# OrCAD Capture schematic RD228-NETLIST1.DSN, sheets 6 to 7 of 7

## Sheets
6 2: size A3
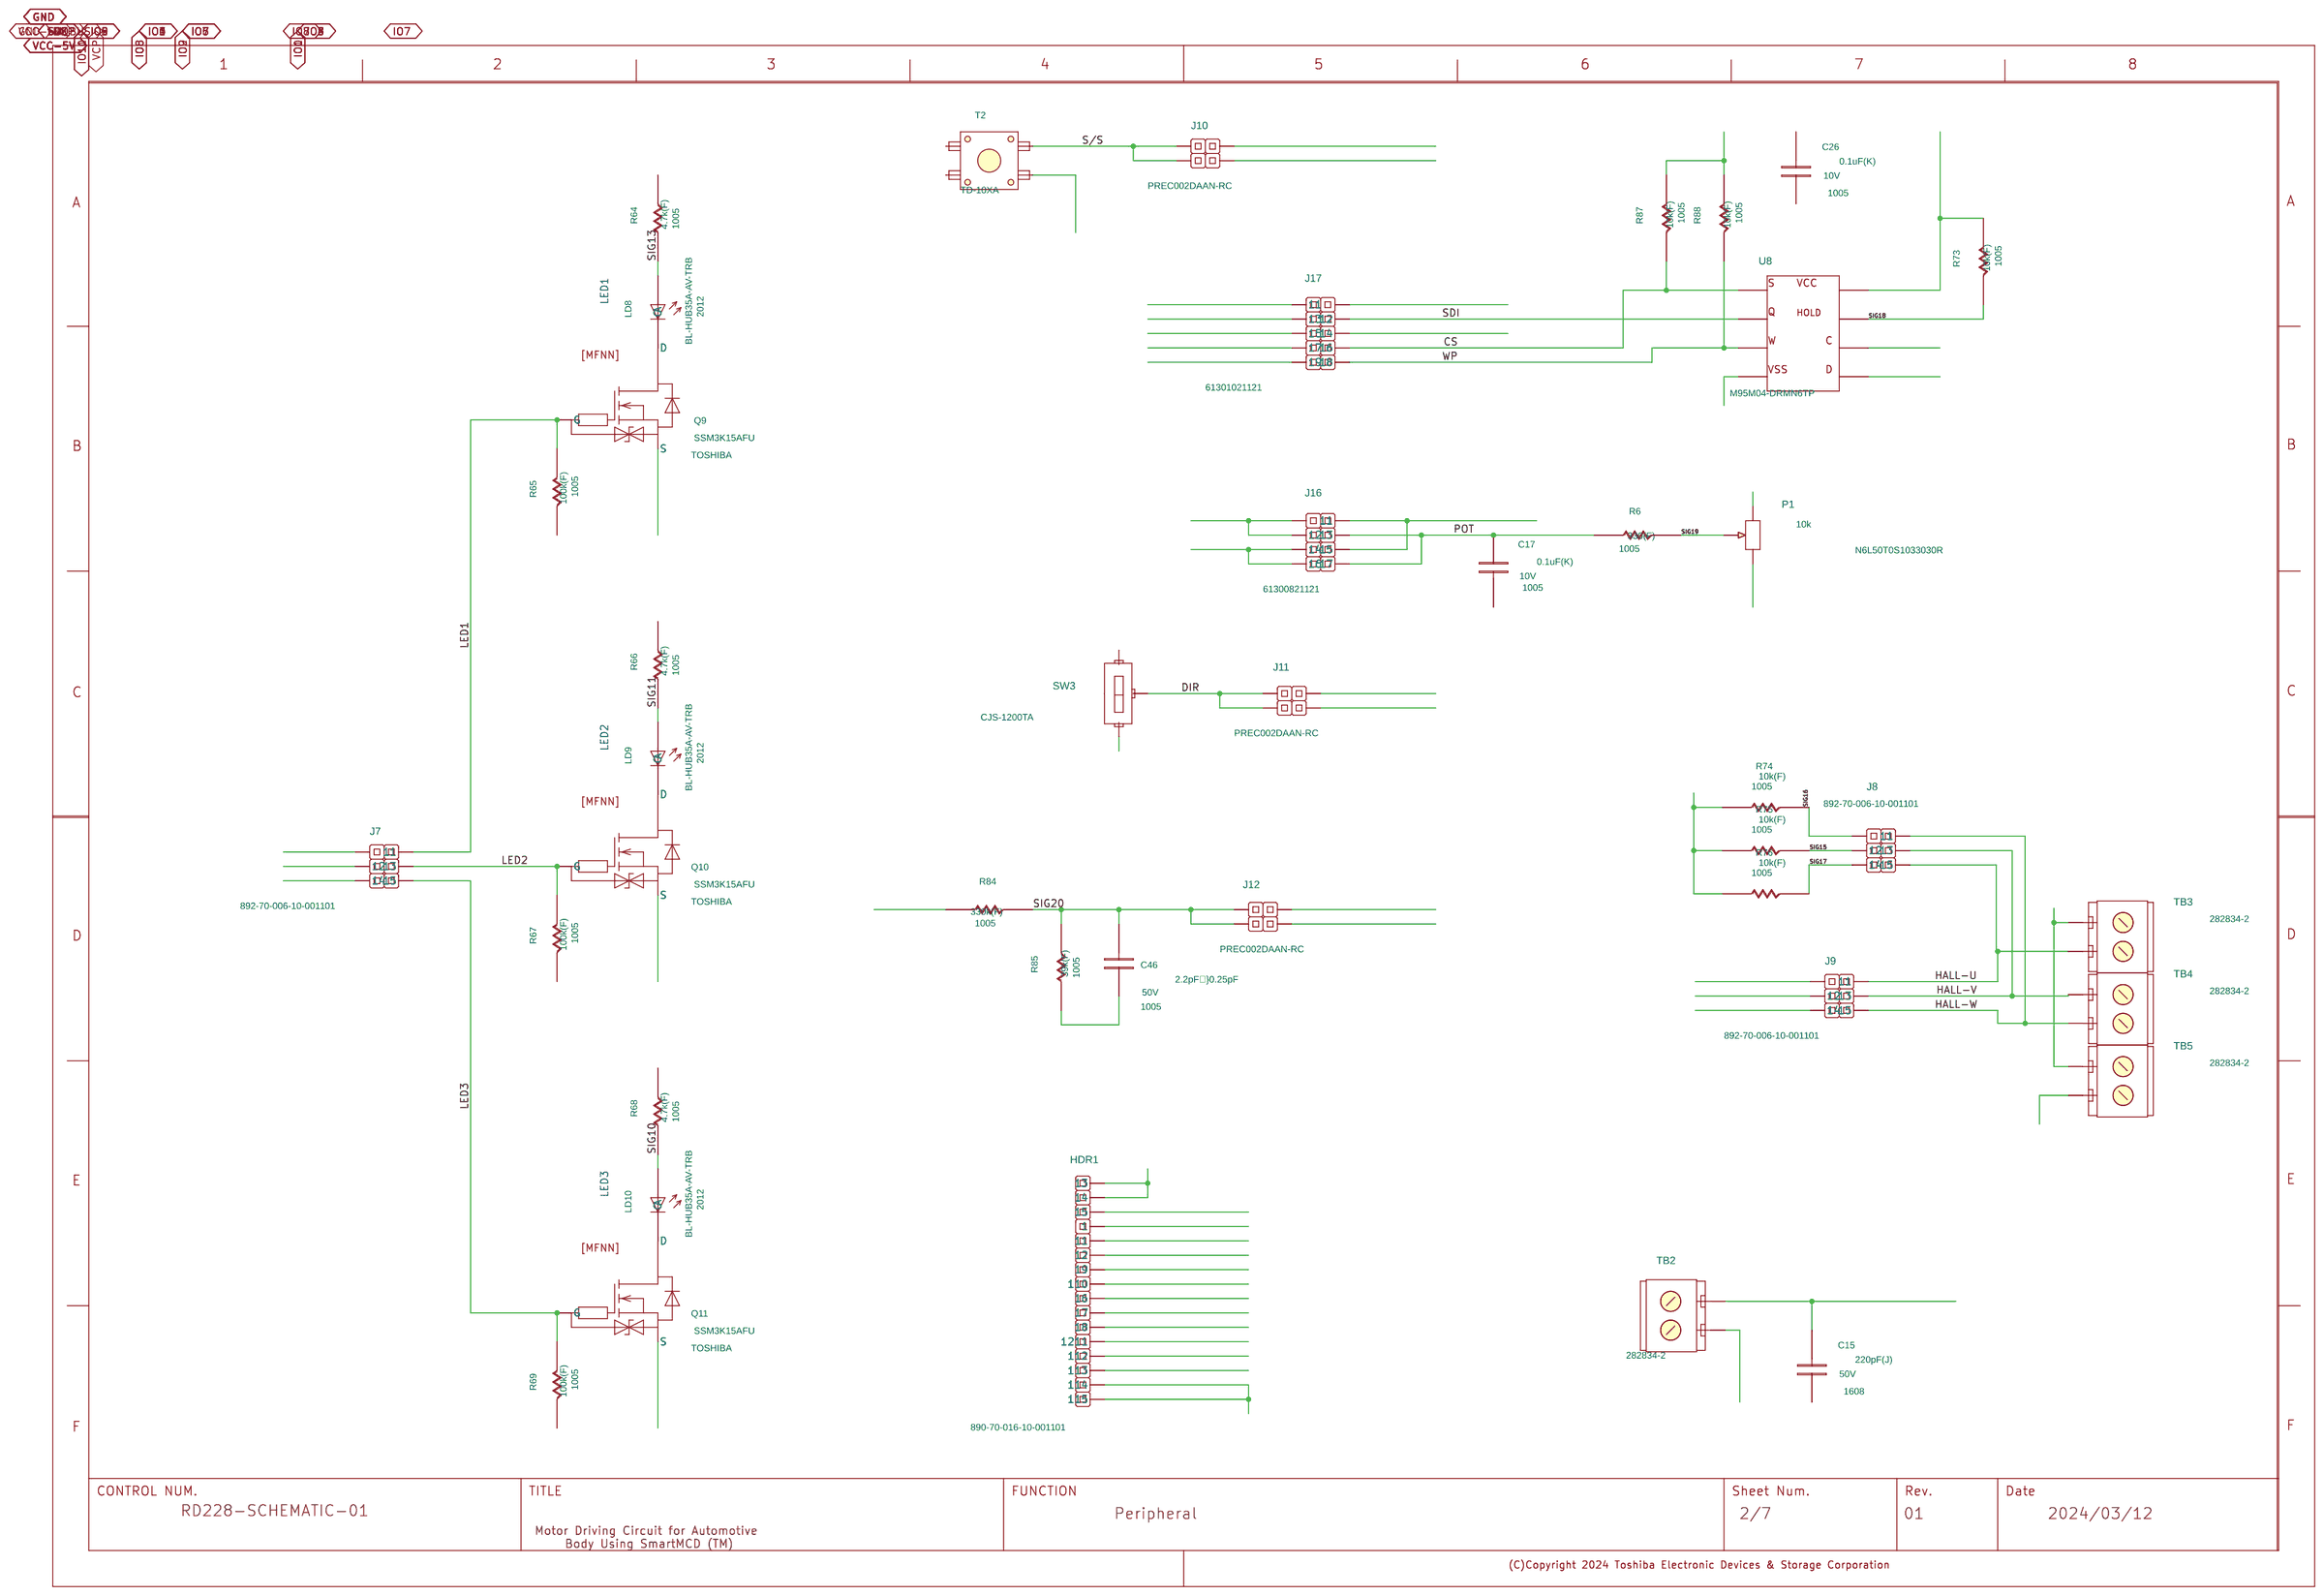
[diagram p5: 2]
7 1: size A3
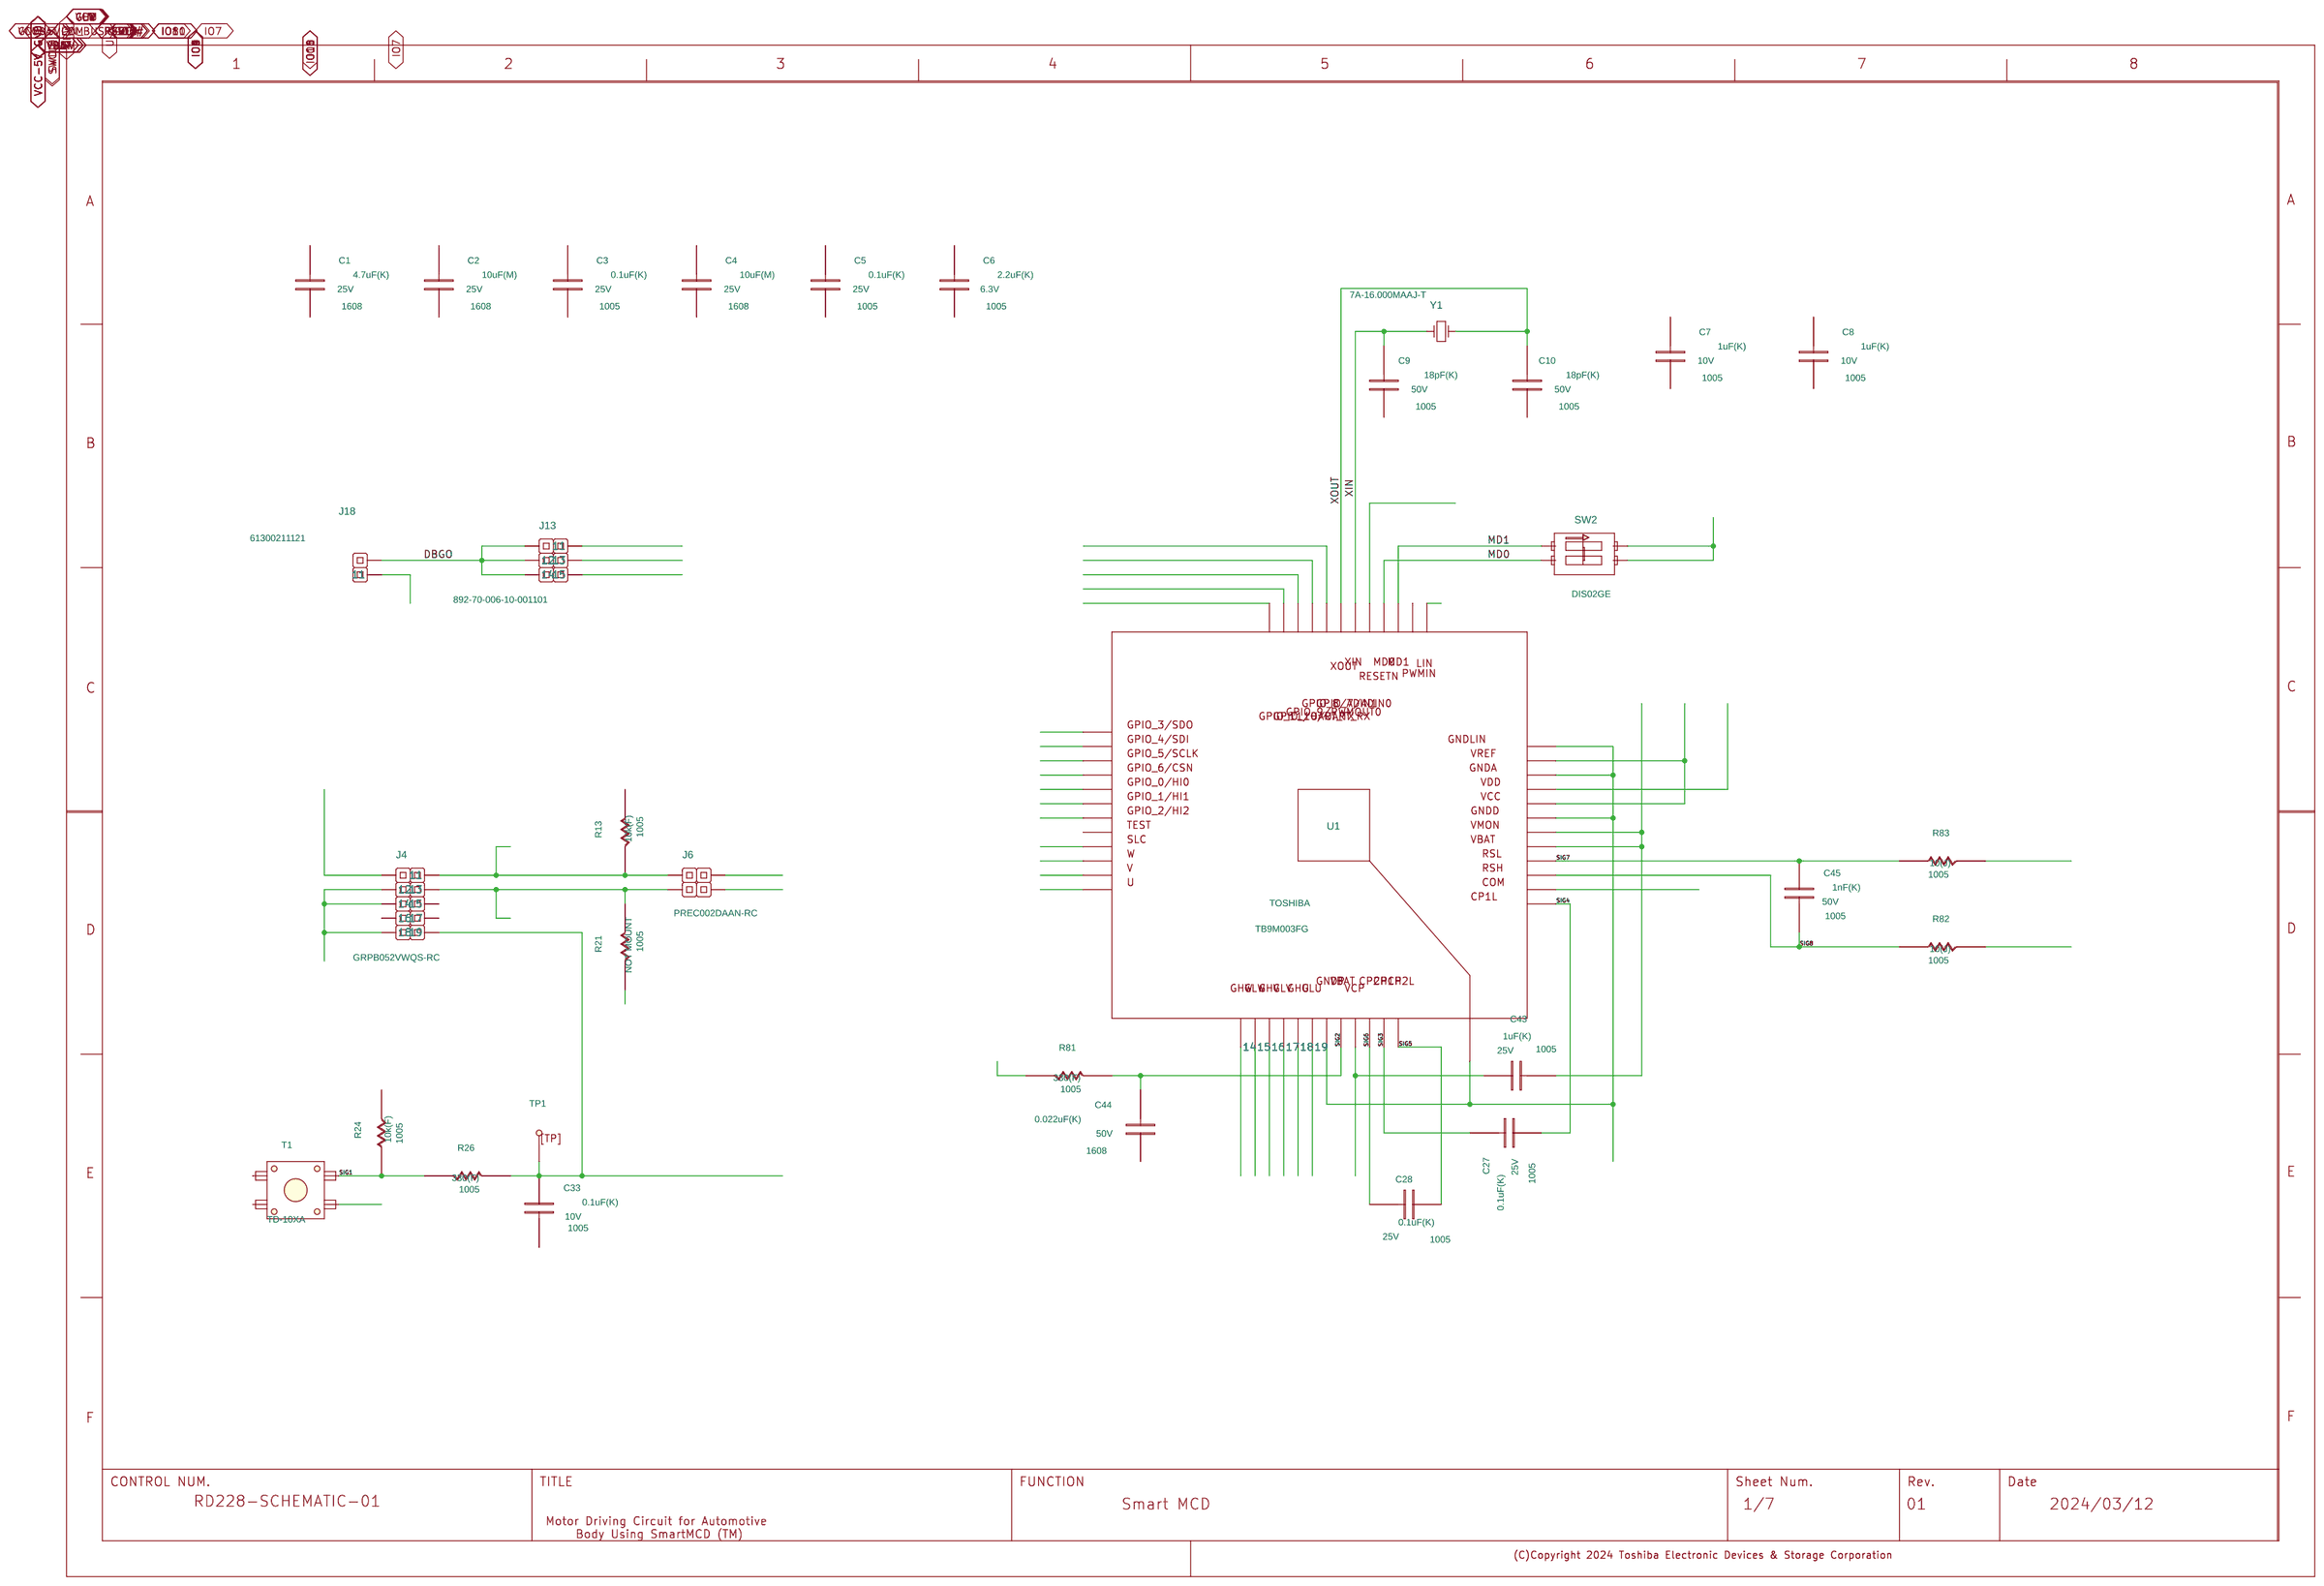
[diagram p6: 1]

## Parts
sheet 1
C1  C
C2  C
C3  C
C4  C
C5  C
C6  C
C7  C
C8  C
C9  C
C10  C
C27  C
C28  C
C33  C
C43  C
C44  C
C45  C
J4  HM2X5
J6  HM 2x2
J13  HM 2x3
J18  M1X2
R13  R
R21  R
R24  R
R26  R
R81  R
R82  R
R83  R
SW2  DIP SW 2 pin
T1  Start/Stop
TP1  TP
U1  NA
U?#6  WAKU_DEF100
Y1  16MHz
sheet 2
C15  C
C17  C
C26  C
C46  C
HDR1  M1X16
J7  HM 2x3
J8  HM 2x3
J9  HM 2x3
J10  HM 2x2
J11  HM 2x2
J12  HM 2x2
J16  HM 2x4
J17  HM2X5
LD8  LED
LD9  LED
LD10  LED
P1  10k  [N6R]
Q9  MFNN
Q10  MFNN
Q11  MFNN
R6  R
R64  R
R65  R
R66  R
R67  R
R68  R
R69  R
R73  R
R74  R
R75  R
R76  R
R84  R
R85  R
R87  R
R88  R
SW3  Direction
T2  Start/Stop
TB2  282834-2
TB3  282834-2
TB4  282834-2
TB5  282834-2
U8  NA
U?#5  WAKU_DEF100

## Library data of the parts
C1 = C: COMPONENTTYPE: 4; LAYOUTNAME: Z-42150c18-033c-4af5-aba7-8ebe0f0e94f5.cmp457; SAVECOUNT: 0; SIZECODESMD: 1608; VAL1: 4.7uF(K); VAL2: 25V
C2 = C: COMPONENTTYPE: 4; LAYOUTNAME: Z-42150c18-033c-4af5-aba7-8ebe0f0e94f5.cmp454; SAVECOUNT: 0; SIZECODESMD: 1608; VAL1: 10uF(M); VAL2: 25V
C3 = C: COMPONENTTYPE: 4; LAYOUTNAME: Z-42150c18-033c-4af5-aba7-8ebe0f0e94f5.cmp443; SAVECOUNT: 0; SIZECODESMD: 1005; VAL1: 0.1uF(K); VAL2: 25V
C4 = C: COMPONENTTYPE: 4; LAYOUTNAME: Z-42150c18-033c-4af5-aba7-8ebe0f0e94f5.cmp446; SAVECOUNT: 0; SIZECODESMD: 1608; VAL1: 10uF(M); VAL2: 25V
C5 = C: COMPONENTTYPE: 4; LAYOUTNAME: Z-42150c18-033c-4af5-aba7-8ebe0f0e94f5.cmp451; SAVECOUNT: 0; SIZECODESMD: 1005; VAL1: 0.1uF(K); VAL2: 25V
C6 = C: COMPONENTTYPE: 4; LAYOUTNAME: Z-42150c18-033c-4af5-aba7-8ebe0f0e94f5.cmp448; SAVECOUNT: 0; SIZECODESMD: 1005; VAL1: 2.2uF(K); VAL2: 6.3V
C7 = C: COMPONENTTYPE: 4; LAYOUTNAME: Z-42150c18-033c-4af5-aba7-8ebe0f0e94f5.cmp521; SAVECOUNT: 0; SIZECODESMD: 1005; VAL1: 1uF(K); VAL2: 10V
C8 = C: COMPONENTTYPE: 4; LAYOUTNAME: Z-42150c18-033c-4af5-aba7-8ebe0f0e94f5.cmp526; SAVECOUNT: 0; SIZECODESMD: 1005; VAL1: 1uF(K); VAL2: 10V
C9 = C: COMPONENTTYPE: 4; LAYOUTNAME: Z-42150c18-033c-4af5-aba7-8ebe0f0e94f5.cmp512; SAVECOUNT: 0; SIZECODESMD: 1005; VAL1: 18pF(K); VAL2: 50V
C10 = C: COMPONENTTYPE: 4; LAYOUTNAME: Z-42150c18-033c-4af5-aba7-8ebe0f0e94f5.cmp514; SAVECOUNT: 0; SIZECODESMD: 1005; VAL1: 18pF(K); VAL2: 50V
C27 = C: COMPONENTTYPE: 4; LAYOUTNAME: Z-42150c18-033c-4af5-aba7-8ebe0f0e94f5.cmp489; SAVECOUNT: 0; SIZECODESMD: 1005; VAL1: 0.1uF(K); VAL2: 25V
C28 = C: COMPONENTTYPE: 4; LAYOUTNAME: Z-42150c18-033c-4af5-aba7-8ebe0f0e94f5.cmp488; SAVECOUNT: 0; SIZECODESMD: 1005; VAL1: 0.1uF(K); VAL2: 25V
C17 C33 = C: COMPONENTTYPE: 4; SAVECOUNT: 0; SIZECODESMD: 1005; VAL1: 0.1uF(K); VAL2: 10V
C43 = C: COMPONENTTYPE: 4; LAYOUTNAME: Z-42150c18-033c-4af5-aba7-8ebe0f0e94f5.cmp492; SAVECOUNT: 0; SIZECODESMD: 1005; VAL1: 1uF(K); VAL2: 25V
C44 = C: COMPONENTTYPE: 4; LAYOUTNAME: Z-42150c18-033c-4af5-aba7-8ebe0f0e94f5.cmp480; SAVECOUNT: 0; SIZECODESMD: 1608; VAL1: 0.022uF(K); VAL2: 50V
C45 = C: COMPONENTTYPE: 4; SAVECOUNT: 0; SIZECODESMD: 1005; VAL1: 1nF(K); VAL2: 50V
J4 = HM_2X5_J4: COMPONENTTYPE: 4; LAYOUTNAME: Z-42150c18-033c-4af5-aba7-8ebe0f0e94f5.cmp422; VAL3: GRPB052VWQS-RC
J6 = HM_2X2_J6: COMPONENTTYPE: 4; LAYOUTNAME: Z-42150c18-033c-4af5-aba7-8ebe0f0e94f5.cmp427; VAL3: PREC002DAAN-RC
J13 = HM_2X3_J13: COMPONENTTYPE: 4; LAYOUTNAME: Z-42150c18-033c-4af5-aba7-8ebe0f0e94f5.cmp430; VAL3: 892-70-006-10-001101
J18 = HM_1X2_J18: COMPONENTTYPE: 4; LAYOUTNAME: Z-42150c18-033c-4af5-aba7-8ebe0f0e94f5.cmp431; VAL3: 61300211121
R13 = R: COMPONENTTYPE: 4; LAYOUTNAME: Z-42150c18-033c-4af5-aba7-8ebe0f0e94f5.cmp425; SAVECOUNT: 0; SIZECODESMD: 1005; VAL1: 10k(F); VAL2: 63mW
R21 = R: COMPONENTTYPE: 4; LAYOUTNAME: Z-42150c18-033c-4af5-aba7-8ebe0f0e94f5.cmp433; NOTMOUNT: NOT MOUNT; SAVECOUNT: 0; SIZECODESMD: 1005; VAL1: 10k(F); VAL2: 63mW
R24 = R: COMPONENTTYPE: 4; SAVECOUNT: 0; SIZECODESMD: 1005; VAL1: 10k(F); VAL2: 63mW
R26 R81 = R: COMPONENTTYPE: 4; SAVECOUNT: 0; SIZECODESMD: 1005; VAL1: 330(F); VAL2: 63mW
R82 = R: COMPONENTTYPE: 4; LAYOUTNAME: Z-42150c18-033c-4af5-aba7-8ebe0f0e94f5.cmp508; SAVECOUNT: 0; SIZECODESMD: 1005; VAL1: 10(J); VAL2: 100mW
R83 = R: COMPONENTTYPE: 4; LAYOUTNAME: Z-42150c18-033c-4af5-aba7-8ebe0f0e94f5.cmp507; SAVECOUNT: 0; SIZECODESMD: 1005; VAL1: 10(J); VAL2: 100mW
SW2 = DIP_SWITCH_2_PIN_SMD_SW2: COMPONENTTYPE: 4; LAYOUTNAME: Z-42150c18-033c-4af5-aba7-8ebe0f0e94f5.cmp518; VAL3: DIS02GE
T1 = TASTER_4P_SPST_NO_T2: COMPONENTTYPE: 4; LAYOUTNAME: Z-42150c18-033c-4af5-aba7-8ebe0f0e94f5.cmp568; VAL3: TD-10XA
TP1 = TP: COMPONENTTYPE: 4; LAYOUTNAME: Z-42150c18-033c-4af5-aba7-8ebe0f0e94f5.cmp418; SAVECOUNT: 5
U1 = TB9M003FG_U1: COMPONENTTYPE: 4; LAYOUTNAME: Z-42150c18-033c-4af5-aba7-8ebe0f0e94f5.cmp465; UPDATEDATE: 2024/3/5; UPDATETIME: 17:09:18; USERCOMPTEXT3: TOSHIBA; VAL3: TB9M003FG
U?#6 = WAKU_DEF100: COMPONENTTYPE: 2; DATE: 2024/03/12; DRAWINGNUMBER: RD228-SCHEMATIC-01; FUNCTION: Smart MCD; LAYOUTNAME: Z-42150c18-033c-4af5-aba7-8ebe0f0e94f5.cmp552; REVISION: 01; SAVEAREA0: 185750,-43960,448537,75779; SAVECOUNT: 9; SHEETNUMBER: 1/7; SHTSAVECOUNT: 46; TITLE: Motor Driving Circuit for Automotive / Body Using SmartMCD (TM); UPDATEDATE: 2024/03/18; UPDATETIME: 15:21:53
Y1 = CRYSTAL_Y1: COMPONENTTYPE: 4; LAYOUTNAME: Z-42150c18-033c-4af5-aba7-8ebe0f0e94f5.cmp515; UPDATEDATE: 2024/2/16; UPDATETIME: 16:56:47; VAL3: 7A-16.000MAAJ-T
C15 = C: COMPONENTTYPE: 4; LAYOUTNAME: Z-e340b0a3-4671-47de-a655-fee0dbe0e92c.cmp107; SAVECOUNT: 0; SIZECODESMD: 1608; VAL1: 220pF(J); VAL2: 50V
C26 = C: COMPONENTTYPE: 4; LAYOUTNAME: Z-e340b0a3-4671-47de-a655-fee0dbe0e92c.cmp157; SAVECOUNT: 0; SIZECODESMD: 1005; VAL1: 0.1uF(K); VAL2: 10V
C46 = C: COMPONENTTYPE: 4; LAYOUTNAME: Z-e340b0a3-4671-47de-a655-fee0dbe0e92c.cmp205; SAVECOUNT: 0; SIZECODESMD: 1005; VAL1: 2.2pF}0.25pF; VAL2: 50V
HDR1 = HM_1X16_HDR1: COMPONENTTYPE: 4; LAYOUTNAME: Z-e340b0a3-4671-47de-a655-fee0dbe0e92c.cmp109; VAL3: 890-70-016-10-001101
J7 = HM_2X3_J7: COMPONENTTYPE: 4; LAYOUTNAME: Z-e340b0a3-4671-47de-a655-fee0dbe0e92c.cmp69; VAL3: 892-70-006-10-001101
J8 = HM_2X3_J7: COMPONENTTYPE: 4; LAYOUTNAME: Z-e340b0a3-4671-47de-a655-fee0dbe0e92c.cmp131; VAL3: 892-70-006-10-001101
J9 = HM_2X3_J7: COMPONENTTYPE: 4; LAYOUTNAME: Z-e340b0a3-4671-47de-a655-fee0dbe0e92c.cmp229; VAL3: 892-70-006-10-001101
J10 = HM_2X2_J10: COMPONENTTYPE: 4; LAYOUTNAME: Z-e340b0a3-4671-47de-a655-fee0dbe0e92c.cmp213; VAL3: PREC002DAAN-RC
J11 = HM_2X2_J11: COMPONENTTYPE: 4; LAYOUTNAME: Z-e340b0a3-4671-47de-a655-fee0dbe0e92c.cmp170; VAL3: PREC002DAAN-RC
J12 = HM_2X2_J12: COMPONENTTYPE: 4; LAYOUTNAME: Z-e340b0a3-4671-47de-a655-fee0dbe0e92c.cmp206; VAL3: PREC002DAAN-RC
J16 = HM_2X4_J16: COMPONENTTYPE: 4; LAYOUTNAME: Z-e340b0a3-4671-47de-a655-fee0dbe0e92c.cmp158; VAL3: 61300821121
J17 = HM_2X5_J17: COMPONENTTYPE: 4; LAYOUTNAME: Z-e340b0a3-4671-47de-a655-fee0dbe0e92c.cmp140; VAL3: 61301021121
LD8 = LED: COMPONENTTYPE: 4; LAYOUTNAME: Z-e340b0a3-4671-47de-a655-fee0dbe0e92c.cmp101; SIZECODESMD: 2012; UPDATEDATE: 06/10/13; UPDATETIME: 13:54:07; UPDATEUSER: fukuda-y; VAL1: RED; VAL3: BL-HUB35A-AV-TRB
LD9 = LED: COMPONENTTYPE: 4; LAYOUTNAME: Z-e340b0a3-4671-47de-a655-fee0dbe0e92c.cmp85; SIZECODESMD: 2012; UPDATEDATE: 06/10/13; UPDATETIME: 13:54:07; UPDATEUSER: fukuda-y; VAL1: RED; VAL3: BL-HUB35A-AV-TRB
LD10 = LED: COMPONENTTYPE: 4; LAYOUTNAME: Z-e340b0a3-4671-47de-a655-fee0dbe0e92c.cmp79; SIZECODESMD: 2012; UPDATEDATE: 06/10/13; UPDATETIME: 13:54:07; UPDATEUSER: fukuda-y; VAL1: RED; VAL3: BL-HUB35A-AV-TRB
P1 = POTENTIOMETER_P1: COMPONENTNAME: Potentiometer_P1_Potentiometer_P1; COMPONENTTYPE: 4; INSTANCENAME: INS5795; LAYOUTNAME: Z-e340b0a3-4671-47de-a655-fee0dbe0e92c.cmp166; VAL2: 100mW; VAL3: N6L50T0S1033030R
Q9 = MFNN: COMP: Q; COMPONENTTYPE: 4; LAYOUTNAME: Z-e340b0a3-4671-47de-a655-fee0dbe0e92c.cmp103; USERCOMPTEXT3: TOSHIBA; VAL3: SSM3K15AFU
Q10 Q11 = MFNN: COMP: Q; COMPONENTTYPE: 4; USERCOMPTEXT3: TOSHIBA; VAL3: SSM3K15AFU
R6 = R: COMPONENTTYPE: 4; LAYOUTNAME: Z-e340b0a3-4671-47de-a655-fee0dbe0e92c.cmp165; SAVECOUNT: 0; SIZECODESMD: 1005; VAL1: 330(F); VAL2: 63mW
R64 R66 R68 = R: COMPONENTTYPE: 4; SAVECOUNT: 0; SIZECODESMD: 1005; VAL1: 4.7k(F); VAL2: 63mW
R65 = R: COMPONENTTYPE: 4; LAYOUTNAME: Z-e340b0a3-4671-47de-a655-fee0dbe0e92c.cmp102; SAVECOUNT: 0; SIZECODESMD: 1005; VAL1: 100k(F); VAL2: 63mW
R67 = R: COMPONENTTYPE: 4; LAYOUTNAME: Z-e340b0a3-4671-47de-a655-fee0dbe0e92c.cmp82; SAVECOUNT: 0; SIZECODESMD: 1005; VAL1: 100k(F); VAL2: 63mW
R69 = R: COMPONENTTYPE: 4; LAYOUTNAME: Z-e340b0a3-4671-47de-a655-fee0dbe0e92c.cmp75; SAVECOUNT: 0; SIZECODESMD: 1005; VAL1: 100k(F); VAL2: 63mW
R73 = R: COMPONENTTYPE: 4; LAYOUTNAME: Z-e340b0a3-4671-47de-a655-fee0dbe0e92c.cmp151; SAVECOUNT: 0; SIZECODESMD: 1005; VAL1: 10k(F); VAL2: 63mW
R74 = R: COMPONENTTYPE: 4; LAYOUTNAME: Z-e340b0a3-4671-47de-a655-fee0dbe0e92c.cmp130; SAVECOUNT: 0; SIZECODESMD: 1005; VAL1: 10k(F); VAL2: 63mW
R75 = R: COMPONENTTYPE: 4; LAYOUTNAME: Z-e340b0a3-4671-47de-a655-fee0dbe0e92c.cmp132; SAVECOUNT: 0; SIZECODESMD: 1005; VAL1: 10k(F); VAL2: 63mW
R76 = R: COMPONENTTYPE: 4; LAYOUTNAME: Z-e340b0a3-4671-47de-a655-fee0dbe0e92c.cmp133; SAVECOUNT: 0; SIZECODESMD: 1005; VAL1: 10k(F); VAL2: 63mW
R84 = R: COMPONENTTYPE: 4; LAYOUTNAME: Z-e340b0a3-4671-47de-a655-fee0dbe0e92c.cmp209; SAVECOUNT: 0; SIZECODESMD: 1005; VAL1: 330k(F); VAL2: 63mW
R85 = R: COMPONENTTYPE: 4; SAVECOUNT: 0; SIZECODESMD: 1005; VAL1: 39k(F); VAL2: 63mW
R87 = R: COMPONENTTYPE: 4; LAYOUTNAME: Z-e340b0a3-4671-47de-a655-fee0dbe0e92c.cmp153; SAVECOUNT: 0; SIZECODESMD: 1005; VAL1: 10k(F); VAL2: 63mW
R88 = R: COMPONENTTYPE: 4; LAYOUTNAME: Z-e340b0a3-4671-47de-a655-fee0dbe0e92c.cmp154; SAVECOUNT: 0; SIZECODESMD: 1005; VAL1: 10k(F); VAL2: 63mW
SW3 = CAS_120TA_SW3: COMPONENTTYPE: 4; LAYOUTNAME: Z-e340b0a3-4671-47de-a655-fee0dbe0e92c.cmp169; VAL3: CJS-1200TA
T2 = TASTER_4P_SPST_NO_T2: COMPONENTTYPE: 4; LAYOUTNAME: Z-e340b0a3-4671-47de-a655-fee0dbe0e92c.cmp231; VAL3: TD-10XA
TB2 = SCREW_TERMINAL_2P_TB2: COMPONENTTYPE: 4; LAYOUTNAME: Z-e340b0a3-4671-47de-a655-fee0dbe0e92c.cmp105
TB3 = SCREW_TERMINAL_2P_TB2: COMPONENTTYPE: 4; LAYOUTNAME: Z-e340b0a3-4671-47de-a655-fee0dbe0e92c.cmp127
TB4 = SCREW_TERMINAL_2P_TB2: COMPONENTTYPE: 4; LAYOUTNAME: Z-e340b0a3-4671-47de-a655-fee0dbe0e92c.cmp125
TB5 = SCREW_TERMINAL_2P_TB2: COMPONENTTYPE: 4; LAYOUTNAME: Z-e340b0a3-4671-47de-a655-fee0dbe0e92c.cmp126
U8 = 3500000277558_U8: COMPONENTTYPE: 4; LAYOUTNAME: Z-e340b0a3-4671-47de-a655-fee0dbe0e92c.cmp146; VAL3: M95M04-DRMN6TP
U?#5 = WAKU_DEF100: AUTHOR: w20165dm; COMPONENTTYPE: 2; DATE: 2024/03/12; DRAWINGNUMBER: RD228-SCHEMATIC-01; FUNCTION: Peripheral; LAYOUTNAME: Z-e340b0a3-4671-47de-a655-fee0dbe0e92c.cmp66; REVISION: 01; SAVEAREA0: 185750,-43960,448537,75779; SAVECOUNT: 9; SHEETNUMBER: 2/7; SHTSAVECOUNT: 44; TIME: 13:11:31; TITLE: Motor Driving Circuit for Automotive / Body Using SmartMCD (TM); UPDATEDATE: 2024/03/26; UPDATETIME: 12:23:00

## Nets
GND: C1.1 C2.1 C3.1 C4.1 C5.1 C6.1 C7.1 C8.1 C9.1 C10.1 C15.1 C17.2 C26.1 C26.2 C33.2 C44.1 C46.1 HDR1.1(13) HDR1.2(14) HDR1.15(114) HDR1.16(115) J4.1 J4.3(12) J4.5(14) J4.9(18) J18.2(11) P1.1 P1.3 Q9.2(S) Q10.2(S) Q11.2(S) R13.1 R21.2 R24.2 R64.2 R65.2 R66.2 R67.2 R68.2 R69.2 R73.1 R74.1 R75.1 R76.1 R85.1 R87.1 R88.1 SW2.3 SW2.4 SW3.1 T1.1 T2.1 TB2.2 TB3.1 TB5.1 TB5.2 U1.19 U1.31 U1.34 U1.36 U1.49 U8.4 U8.8 ; also on sheet 1 2 3 4 5
VBAT: C1.2 C2.2 C3.2 C4.2 C5.2 C43.2 R81.2 U1.29 U1.30 ; also on sheet 1 2
VDD: C6.2 U1.33
COM: U1.26 ; also on sheet 2
CS: J17.7(16) R87.2 U8.1
DBGO: J13.1 J13.3(12) J13.5(14) J18.1
DIR: J11.1 J11.3 SW3.2
GHU: U1.17(18) ; also on sheet 2
GHV: U1.15(16) ; also on sheet 2
GHW: U1.13(14) ; also on sheet 2
GLU: U1.18(19) ; also on sheet 2
GLV: U1.16(17) ; also on sheet 2
GLW: U1.14(15) ; also on sheet 2
HALL-U: J8.6(15) J9.2(11) TB3.2
HALL-V: J8.4(13) J9.4(13) TB4.1
HALL-W: J8.2(11) J9.6(15) TB4.2
IO0: HDR1.3(15) J9.1 U1.5 ; also on sheet 5
IO1: HDR1.4(1) J9.3(12) U1.6 ; also on sheet 5
IO2: HDR1.5(11) J9.5(14) U1.7
IO3: HDR1.6(12) J17.2(11) U1.1 ; also on sheet 5
IO4: HDR1.7(19) J17.4(13) U1.2 ; also on sheet 5
IO5: HDR1.8(110) J17.6(15) U1.3
IO6: HDR1.9(16) J17.8(17) U1.4
IO7: HDR1.10(17) J7.1 J10.2 J12.2 J13.2(11) J16.1 J16.3(12) J17.10(19) U1.44 ; also on sheet 3 5
IO8: HDR1.11(18) J7.3(12) J11.2 J12.4 J13.4(13) J16.5(14) J16.7(16) U1.45 ; also on sheet 5
IO9: HDR1.12(1211) J7.5(14) J10.4 J11.4 J13.6(15) U1.46
IO10: HDR1.13(112) J6.2 U1.47 ; also on sheet 5
IO11: HDR1.14(113) J6.4 U1.48 ; also on sheet 5
LED1: J7.2(11) Q9.1(G) R65.1
LED2: J7.4(13) Q10.1(G) R67.1
LED3: J7.6(15) Q11.1(G) R69.1
LIN_BUS: C15.2 TB2.1 U1.37
MD0: SW2.2 U1.40
MD1: SW2.1 U1.39
POT: C17.1 J16.4(13) J16.8(17) R6.1
RESET#: C33.1 J4.10(19) R26.1 TP1.1 U1.41 ; also on sheet 4
RSH: R82.2 ; also on sheet 2 3
RSL: R83.2 ; also on sheet 2 3
S/S: J10.1 J10.3 T2.2
SCK: J17.5(14) U8.6
SDI: J17.3(12) U8.2
SDO: J17.1 U8.5
SIG1: R24.1 R26.2 T1.2
SIG2: C44.2 R81.1 U1.20
SIG3: C27.2 U1.23
SIG4: C27.1 U1.25
SIG5: C28.1 U1.24
SIG6: C28.2 U1.22
SIG7: C45.1 R83.1 U1.28
SIG8: C45.2 R82.1 U1.27
SIG10: LD10.2(A) R68.1
SIG11: LD9.2(A) R66.1
SIG13: LD8.2(A) R64.1
SIG15: J8.3(12) R75.2
SIG16: J8.1 R74.2
SIG17: J8.5(14) R76.2
SIG18: R73.2 U8.7
SIG19: P1.2 R6.2
SIG20: C46.2 J12.1 J12.3 R84.2 R85.2
SLC: U1.9 ; also on sheet 2
SWCLK: J4.4(13) J6.3 R21.1 ; also on sheet 4
SWDIO: J4.2(11) J6.1 R13.2 ; also on sheet 4
TEMP: J16.2(11) J16.6(15) ; also on sheet 2
U: U1.12 ; also on sheet 2
V: U1.11 ; also on sheet 2
V-5V: C7.2 C8.2 U1.32 U1.35
VCP: C43.1 R84.1 U1.21
W: U1.10 ; also on sheet 2
WP: J17.9(18) R88.2 U8.3
XIN: C9.2 U1.42 Y1.1
XOUT: C10.2 U1.43 Y1.2
N03579: LD8.1(C) Q9.3(D)
N03580: LD9.1(C) Q10.3(D)
N03581: LD10.1(C) Q11.3(D)

Not connected (* = marked no-connect by the designer): J4 6(15) 7(16) 8(17); SW3 3; T1 3 4; T2 3 4; U1 8 38

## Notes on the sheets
sheet 6
- LED1
- LED2
- LED3
